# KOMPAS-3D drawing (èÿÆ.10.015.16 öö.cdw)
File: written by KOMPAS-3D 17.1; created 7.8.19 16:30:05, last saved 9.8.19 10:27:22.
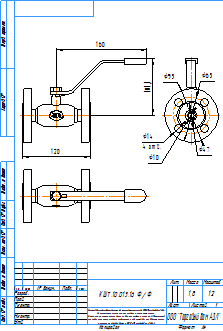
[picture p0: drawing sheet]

Sheet 1: A4, portrait

Title block, sheet 1: name: КШТ.10.015.16 Ф/Ф; material: Сталь 20  ГОСТ 1050-2013; mass: 1,8; sheets: 1; sheet format: A4; stored path: C:\Users\kka\KOMPAS_Work\Модели кранов для исследований\DN65\КШТ.10.065.16 СС.cdw

Views: Вид 1, Проекционный вид 2, Проекционный вид 3
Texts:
  kka
  adl
  Рама для чертежей
  Лит-Масса-Масштаб
  Материал-Предприятие
  Масштаб
  Изм.
  Лист
  № докум.
  Подп.
  Дата
  Лит.
  Разраб.
  Пров.
  Т.контр.
  Листов
  Внимание! Данный продукт является объектом авторского права ООО «Торговый Дом АДЛ».
  Запрещается изменение, копирование, распространение
  (в том числе путем копирования на другие сайты и ресурсы в Интернете)
  или любое иное использование информации и объектов без предварительного
  согласия правообладателя (ООО «Торговый Дом АДЛ»).
  Н.контр.
  Утв.
  ООО "Торговый дом АДЛ"
  Изменение
  Номер документа
  Подпись
  Обозначение документа
  Наименование изделия
  Масса изделия по ГОСТ 2.109-73
  Порядковый номер листа
  Общее количество листов в документе
  Характер работы, выполненной лицом, подписавшим документ
  Наименование или индекс предприятия, выпускающего документ
  Инв. № подл.
  Подп. и дата
  Взам. инв. №
  Инв. № дубл.
  Инвентарный номер подлинника по ГОСТ 2.501-68
  Подпись принявшего подлинник в отдел технической документации
  Инвентарный номер подлинника, взамен которого выпущен данный подлинник
  Инвентарный номер дубликата по ГОСТ 2.502-68
  Подпись принявшего дубликат в отдел технической документации
  Справ. №
  Перв. примен.
  Обозначение документа, взамен или на основании которого выпущен данный документ
  Обозначение документа, в котором впервые записан данный документ
  Подпись лица, копировавшего чертеж
  Обозначение формата листа
  !Рама для чертежа
Dimensions and other numbers on the sheet: 160; 101,1; 120; 65; 10; 95; 47; 14; 4 отв.; 1:2; 1; 1,8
